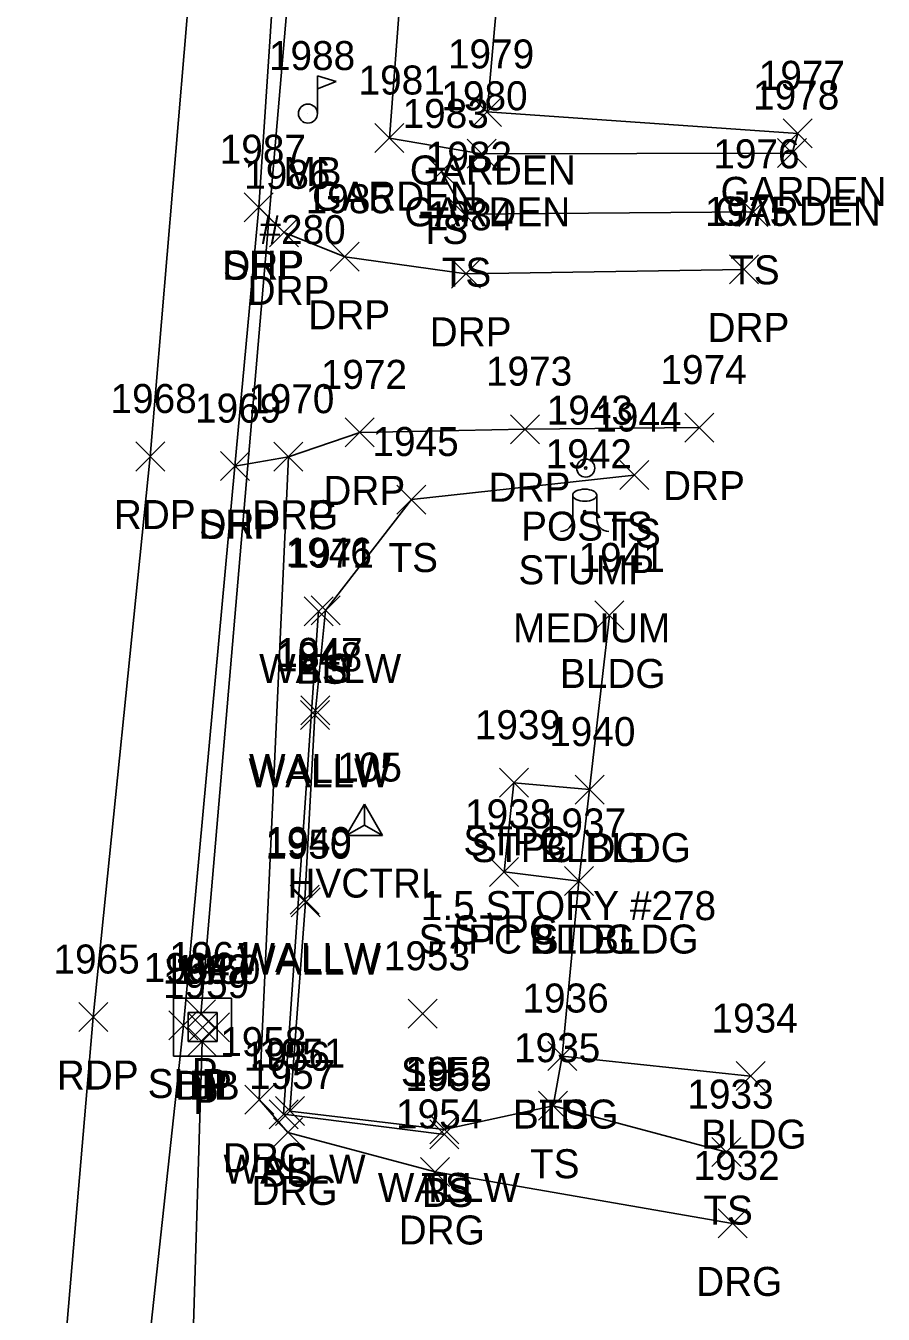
# Model space of a CAD drawing. Extents: x 1653908 to 1654393, y 539913 to 544256.
# Drawn here: x 1654094.1 to 1654153.2, y 541814.4 to 541903.2 of the extents above; entities that cross this region are included whole.
import ezdxf

# ---------------------------------------------------------------- set-up
doc = ezdxf.new("R2010")
doc.units = 0
for name, color, linetype in [('C_A', 7, 'Continuous'), ('C_I', 7, 'Continuous'), ('CPSM', 7, 'Continuous'), ('D_A', 7, 'Continuous'), ('D_I', 7, 'Continuous'), ('D_TIC', 7, 'Continuous'), ('DCP', 7, 'Continuous'), ('DS', 7, 'Continuous'), ('L_A', 7, 'Continuous'), ('L_C', 7, 'Continuous'), ('L_I', 7, 'Continuous'), ('L_TIC', 7, 'Continuous'), ('LAPB', 7, 'Continuous'), ('LBC', 7, 'Continuous'), ('LBF', 7, 'Continuous'), ('LELB', 7, 'Continuous'), ('LMB', 7, 'Continuous'), ('LPST', 7, 'Continuous'), ('LTS', 7, 'Continuous'), ('LW', 7, 'Continuous'), ('P_A', 7, 'Continuous'), ('P_I', 7, 'Continuous'), ('P_TIC', 7, 'Continuous'), ('PET', 7, 'Continuous'), ('PSP', 7, 'Continuous'), ('R_A', 7, 'Continuous'), ('R_I', 7, 'Continuous'), ('R_TIC', 7, 'Continuous'), ('RDG', 7, 'Continuous'), ('RDP', 7, 'Continuous')]:
    doc.layers.add(name, color=color, linetype=linetype)

msp = doc.modelspace()

# ---------------------------------------------------------------- linework, layer by layer
at = {"layer": 'CPSM'}
for p, q in [((1654116.189, 541847.419), (1654117.439, 541849.584)), ((1654118.689, 541847.419), (1654117.439, 541849.584)), ((1654117.439, 541848.141), (1654117.439, 541849.584)), ((1654116.189, 541847.419), (1654117.439, 541848.141)), ((1654117.439, 541848.141), (1654117.439, 541848.141)), ((1654117.439, 541848.141), (1654118.689, 541847.419)), ((1654116.189, 541847.419), (1654118.689, 541847.419))]:
    msp.add_line(p, q, dxfattribs=at)
at = {"layer": 'D_TIC'}
for points in [[(1654105.161, 541834.083), (1654107.161, 541836.083)], [(1654107.161, 541834.083), (1654105.161, 541836.083)], [(1654105.279, 541833.2), (1654107.279, 541835.2)], [(1654107.279, 541833.2), (1654105.279, 541835.2)], [(1654106.144, 541833.193), (1654108.144, 541835.193)], [(1654108.144, 541833.193), (1654106.144, 541835.193)], [(1654105.243, 541832.218), (1654107.243, 541834.218)], [(1654107.243, 541832.218), (1654105.243, 541834.218)]]:
    msp.add_lwpolyline(points, dxfattribs=at)
at = {"layer": 'DCP'}
for points in [[(1654106.161, 541835.083), (1654119.744, 541993.79)], [(1654099.929, 541626.87), (1654106.243, 541833.218)]]:
    msp.add_lwpolyline(points, dxfattribs=at)
at = {"layer": 'DS'}
for p, q in [((1654104.279, 541836.218), (1654108.279, 541836.218)), ((1654104.279, 541832.218), (1654104.279, 541836.218)), ((1654108.279, 541836.218), (1654108.279, 541832.218)), ((1654105.279, 541833.218), (1654105.279, 541835.218)), ((1654105.279, 541835.218), (1654107.279, 541835.218)), ((1654107.279, 541835.218), (1654107.279, 541833.218)), ((1654106.284, 541834.22), (1654106.284, 541834.22)), ((1654106.284, 541834.22), (1654106.284, 541834.22)), ((1654107.279, 541833.218), (1654105.279, 541833.218)), ((1654108.279, 541832.218), (1654104.279, 541832.218))]:
    msp.add_line(p, q, dxfattribs=at)
at = {"layer": 'L_TIC'}
for points in [[(1654124.903, 541896.3), (1654126.903, 541898.3)], [(1654126.903, 541896.3), (1654124.903, 541898.3)], [(1654118.161, 541894.504), (1654120.161, 541896.504)], [(1654120.161, 541894.504), (1654118.161, 541896.504)], [(1654146.333, 541894.826), (1654148.333, 541896.826)], [(1654148.333, 541894.826), (1654146.333, 541896.826)], [(1654146.333, 541894.826), (1654148.333, 541896.826)], [(1654148.333, 541894.826), (1654146.333, 541896.826)], [(1654124.528, 541893.416), (1654126.528, 541895.416)], [(1654126.528, 541893.416), (1654124.528, 541895.416)], [(1654145.94, 541893.469), (1654147.94, 541895.469)], [(1654147.94, 541893.469), (1654145.94, 541895.469)], [(1654121.766, 541892.198), (1654123.766, 541894.198)], [(1654123.766, 541892.198), (1654121.766, 541894.198)], [(1654123.364, 541889.248), (1654125.364, 541891.248)], [(1654125.364, 541889.248), (1654123.364, 541891.248)], [(1654143.256, 541889.415), (1654145.256, 541891.415)], [(1654145.256, 541889.415), (1654143.256, 541891.415)], [(1654135.058, 541871.272), (1654137.058, 541873.272)], [(1654137.058, 541871.272), (1654135.058, 541873.272)], [(1654119.689, 541869.583), (1654121.689, 541871.583)], [(1654121.689, 541869.583), (1654119.689, 541871.583)], [(1654113.275, 541861.879), (1654115.275, 541863.879)], [(1654115.275, 541861.879), (1654113.275, 541863.879)], [(1654113.76, 541861.944), (1654115.76, 541863.944)], [(1654115.76, 541861.944), (1654113.76, 541863.944)], [(1654113.76, 541861.944), (1654115.76, 541863.944)], [(1654115.76, 541861.944), (1654113.76, 541863.944)], [(1654133.337, 541861.593), (1654135.337, 541863.593)], [(1654135.337, 541861.593), (1654133.337, 541863.593)], [(1654113.028, 541854.738), (1654115.028, 541856.738)], [(1654115.028, 541854.738), (1654113.028, 541856.738)], [(1654113.065, 541855.045), (1654115.065, 541857.045)], [(1654115.065, 541855.045), (1654113.065, 541857.045)], [(1654126.757, 541850.059), (1654128.757, 541852.059)], [(1654128.757, 541850.059), (1654126.757, 541852.059)], [(1654131.967, 541849.586), (1654133.967, 541851.586)], [(1654133.967, 541849.586), (1654131.967, 541851.586)], [(1654131.967, 541849.586), (1654133.967, 541851.586)], [(1654133.967, 541849.586), (1654131.967, 541851.586)], [(1654126.074, 541843.911), (1654128.074, 541845.911)], [(1654128.074, 541843.911), (1654126.074, 541845.911)], [(1654131.237, 541843.284), (1654133.237, 541845.284)], [(1654133.237, 541843.284), (1654131.237, 541845.284)], [(1654131.237, 541843.284), (1654133.237, 541845.284)], [(1654133.237, 541843.284), (1654131.237, 541845.284)], [(1654112.331, 541842.001), (1654114.331, 541844.001)], [(1654114.331, 541842.001), (1654112.331, 541844.001)], [(1654112.379, 541841.825), (1654114.379, 541843.825)], [(1654114.379, 541841.825), (1654112.379, 541843.825)], [(1654120.468, 541834.131), (1654122.468, 541836.131)], [(1654122.468, 541834.131), (1654120.468, 541836.131)], [(1654130.089, 541831.217), (1654132.089, 541833.217)], [(1654132.089, 541831.217), (1654130.089, 541833.217)], [(1654130.089, 541831.217), (1654132.089, 541833.217)], [(1654132.089, 541831.217), (1654130.089, 541833.217)], [(1654143.073, 541829.834), (1654145.073, 541831.834)], [(1654145.073, 541829.834), (1654143.073, 541831.834)], [(1654129.452, 541827.794), (1654131.452, 541829.794)], [(1654131.452, 541827.794), (1654129.452, 541829.794)], [(1654129.452, 541827.794), (1654131.452, 541829.794)], [(1654131.452, 541827.794), (1654129.452, 541829.794)], [(1654110.869, 541827.203), (1654112.869, 541829.203)], [(1654112.869, 541827.203), (1654110.869, 541829.203)], [(1654111.303, 541827.419), (1654113.303, 541829.419)], [(1654113.303, 541827.419), (1654111.303, 541829.419)], [(1654121.946, 541826.162), (1654123.946, 541828.162)], [(1654123.946, 541826.162), (1654121.946, 541828.162)], [(1654121.946, 541826.162), (1654123.946, 541828.162)], [(1654123.946, 541826.162), (1654121.946, 541828.162)], [(1654121.963, 541825.816), (1654123.963, 541827.816)], [(1654123.963, 541825.816), (1654121.963, 541827.816)], [(1654141.407, 541824.595), (1654143.407, 541826.595)], [(1654143.407, 541824.595), (1654141.407, 541826.595)]]:
    msp.add_lwpolyline(points, dxfattribs=at)
at = {"layer": 'LAPB'}
for points in [[(1654147.333, 541895.826), (1654146.94, 541894.469), (1654125.528, 541894.416), (1654119.161, 541895.504), (1654120.598, 541914.299), (1654125.073, 541965.48)], [(1654147.333, 541895.826), (1654125.903, 541897.3), (1654127.425, 541914.47), (1654127.843, 541926.277), (1654125.891, 541926.542), (1654128.413, 541965.634), (1654125.073, 541965.48)]]:
    msp.add_lwpolyline(points, dxfattribs=at)
at = {"layer": 'LBC'}
msp.add_lwpolyline([(1654144.073, 541830.834), (1654131.089, 541832.217), (1654132.237, 541844.284), (1654132.967, 541850.586), (1654134.337, 541862.593)], dxfattribs=at)
at = {"layer": 'LBF'}
msp.add_lwpolyline([(1654132.237, 541844.284), (1654127.074, 541844.911), (1654127.757, 541851.059), (1654132.967, 541850.586)], dxfattribs=at)
at = {"layer": 'LELB'}
for points in [[(1654144.256, 541890.415), (1654124.364, 541890.248), (1654122.766, 541893.198)], [(1654136.058, 541872.272), (1654120.689, 541870.583), (1654114.76, 541862.944)], [(1654122.963, 541826.816), (1654111.869, 541828.203), (1654114.275, 541862.879)], [(1654130.452, 541828.794), (1654131.089, 541832.217)], [(1654142.407, 541825.595), (1654130.452, 541828.794), (1654122.946, 541827.162)]]:
    msp.add_lwpolyline(points, dxfattribs=at)
at = {"layer": 'LMB'}
for p, q in [((1654114.197, 541899.788), (1654115.491, 541899.406)), ((1654114.203, 541897.196), (1654114.202, 541899.791)), ((1654114.202, 541898.889), (1654115.484, 541899.397)), ((1654113.547, 541897.188), (1654113.547, 541897.188))]:
    msp.add_line(p, q, dxfattribs=at)
msp.add_circle((1654113.547, 541897.188), 0.656, dxfattribs=at)
at = {"layer": 'LPST'}
for radius in [0.625, 0.0833]:
    msp.add_circle((1654132.706, 541872.749), radius, dxfattribs=at)
at = {"layer": 'LTS'}
for p, q in [((1654131.808, 541870.878), (1654131.808, 541869.211)), ((1654133.475, 541870.711), (1654133.475, 541870.878)), ((1654133.475, 541870.878), (1654133.475, 541869.211)), ((1654132.641, 541869.736), (1654132.641, 541869.736)), ((1654132.641, 541869.736), (1654132.641, 541869.736)), ((1654132.641, 541869.711), (1654132.641, 541869.711))]:
    msp.add_line(p, q, dxfattribs=at)
msp.add_circle((1654132.641, 541869.736), 0.0833, dxfattribs=at)
for centre, start, end in [((1654130.975, 541869.211), 270, 360), ((1654134.308, 541869.211), 180, 270)]:
    msp.add_arc(centre, 0.833, start, end, dxfattribs=at)
msp.add_ellipse((1654132.641, 541870.878), major_axis=(-0.833, 0), ratio=0.5, dxfattribs=at)
at = {"layer": 'LW'}
msp.add_lwpolyline([(1654114.76, 541862.944), (1654114.065, 541856.045), (1654114.028, 541855.738), (1654113.331, 541843.001), (1654113.379, 541842.825), (1654112.303, 541828.419), (1654122.946, 541827.162)], dxfattribs=at)
at = {"layer": 'P_TIC'}
for points in [[(1654109.153, 541889.734), (1654111.153, 541891.734)], [(1654111.153, 541889.734), (1654109.153, 541891.734)], [(1654101.668, 541872.549), (1654103.668, 541874.549)], [(1654103.668, 541872.549), (1654101.668, 541874.549)], [(1654107.508, 541871.884), (1654109.508, 541873.884)], [(1654109.508, 541871.884), (1654107.508, 541873.884)], [(1654097.735, 541833.906), (1654099.735, 541835.906)], [(1654099.735, 541833.906), (1654097.735, 541835.906)], [(1654103.956, 541833.324), (1654105.956, 541835.324)], [(1654105.956, 541833.324), (1654103.956, 541835.324)]]:
    msp.add_lwpolyline(points, dxfattribs=at)
at = {"layer": 'PET'}
msp.add_lwpolyline([(1654079.776, 541659.551), (1654080.091, 541663.585), (1654084.434, 541705.035), (1654088.467, 541726.588), (1654090.823, 541750.421), (1654095.245, 541793.922), (1654098.735, 541834.906), (1654102.668, 541873.549), (1654106.19, 541915.359), (1654108.801, 541937.78), (1654112.78, 541976.541), (1654113.712, 541994.764), (1654118.507, 542040.261), (1654122.37, 542081.456), (1654125.512, 542120.567), (1654128.858, 542154.493), (1654132.07, 542197.521), (1654136.387, 542232.744)], dxfattribs=at)
at = {"layer": 'PSP'}
msp.add_lwpolyline([(1654094.458, 541721.214), (1654096.104, 541749.586), (1654101.261, 541800.15), (1654104.956, 541834.324), (1654108.508, 541872.884), (1654110.153, 541890.734), (1654111.767, 541915.009), (1654113.741, 541937.092), (1654116.462, 541969.541), (1654117.65, 541994.217), (1654121.735, 542040.282), (1654126.757, 542081.182), (1654129.731, 542120.034), (1654133.658, 542152.736), (1654138.064, 542196.396), (1654141.276, 542231.97)], dxfattribs=at)
at = {"layer": 'R_TIC'}
for points in [[(1654109.153, 541889.734), (1654111.153, 541891.734)], [(1654111.153, 541889.734), (1654109.153, 541891.734)], [(1654110.899, 541888.002), (1654112.899, 541890.002)], [(1654112.899, 541888.002), (1654110.899, 541890.002)], [(1654115.084, 541886.319), (1654117.084, 541888.319)], [(1654117.084, 541886.319), (1654115.084, 541888.319)], [(1654123.456, 541885.146), (1654125.456, 541887.146)], [(1654125.456, 541885.146), (1654123.456, 541887.146)], [(1654142.618, 541885.446), (1654144.618, 541887.446)], [(1654144.618, 541885.446), (1654142.618, 541887.446)], [(1654116.124, 541874.211), (1654118.124, 541876.211)], [(1654118.124, 541874.211), (1654116.124, 541876.211)], [(1654127.517, 541874.433), (1654129.517, 541876.433)], [(1654129.517, 541874.433), (1654127.517, 541876.433)], [(1654139.551, 541874.539), (1654141.551, 541876.539)], [(1654141.551, 541874.539), (1654139.551, 541876.539)], [(1654111.2, 541872.535), (1654113.2, 541874.535)], [(1654113.2, 541872.535), (1654111.2, 541874.535)], [(1654111.2, 541872.535), (1654113.2, 541874.535)], [(1654113.2, 541872.535), (1654111.2, 541874.535)], [(1654107.508, 541871.884), (1654109.508, 541873.884)], [(1654109.508, 541871.884), (1654107.508, 541873.884)], [(1654109.188, 541828.211), (1654111.188, 541830.211)], [(1654111.188, 541828.211), (1654109.188, 541830.211)], [(1654111.167, 541825.952), (1654113.167, 541827.952)], [(1654113.167, 541825.952), (1654111.167, 541827.952)], [(1654121.316, 541823.226), (1654123.316, 541825.226)], [(1654123.316, 541823.226), (1654121.316, 541825.226)], [(1654141.833, 541819.68), (1654143.833, 541821.68)], [(1654143.833, 541819.68), (1654141.833, 541821.68)]]:
    msp.add_lwpolyline(points, dxfattribs=at)
at = {"layer": 'RDG'}
msp.add_lwpolyline([(1654142.833, 541820.68), (1654122.316, 541824.226), (1654112.167, 541826.952), (1654110.188, 541829.211), (1654112.2, 541873.535)], dxfattribs=at)
at = {"layer": 'RDP'}
for points in [[(1654143.618, 541886.446), (1654124.456, 541886.146), (1654116.084, 541887.319), (1654111.899, 541889.002), (1654110.153, 541890.734)], [(1654108.508, 541872.884), (1654112.2, 541873.535), (1654117.124, 541875.211), (1654128.517, 541875.433), (1654140.551, 541875.539)]]:
    msp.add_lwpolyline(points, dxfattribs=at)

# ---------------------------------------------------------------- texts
at = {"layer": 'C_A'}
msp.add_text('HVCTRL', height=2, dxfattribs=at).set_placement((1654112.132, 541843.141))
at = {"layer": 'C_I'}
msp.add_text('105', height=2, dxfattribs=at).set_placement((1654115.565, 541851.141))
at = {"layer": 'D_A'}
for s, p in [('P', (1654105.539, 541830.083)), ('DIB', (1654104.381, 541829.2)), ('DI', (1654105.339, 541829.22)), ('P', (1654106.522, 541829.193)), ('P', (1654105.621, 541828.218))]:
    msp.add_text(s, height=2, dxfattribs=at).set_placement(p)
at = {"layer": 'D_I'}
for s, p in [('1961', (1654103.988, 541838.083)), ('1962', (1654103.539, 541837.2)), ('1963', (1654103.544, 541837.22)), ('1960', (1654104.318, 541837.193)), ('1959', (1654103.543, 541836.218))]:
    msp.add_text(s, height=2, dxfattribs=at).set_placement(p)
at = {"layer": 'L_A'}
for s, p in [('MB', (1654111.854, 541892.188)), ('GARDEN', (1654120.572, 541892.3)), ('GARDEN', (1654142.002, 541890.826)), ('GARDEN', (1654142.002, 541890.826)), ('GARDEN', (1654113.831, 541890.504)), ('GARDEN', (1654120.197, 541889.416)), ('GARDEN', (1654141.609, 541889.469)), ('TS', (1654121.176, 541888.198)), ('TS', (1654122.774, 541885.248)), ('TS', (1654142.666, 541885.415)), ('POSTS', (1654128.25, 541867.749)), ('TS', (1654134.467, 541867.272)), ('TS', (1654119.098, 541865.583)), ('STUMP', (1654128.062, 541864.738)), ('WALLW', (1654110.177, 541857.944)), ('BS', (1654112.716, 541857.879)), ('TS', (1654113.169, 541857.944)), ('BLDG', (1654130.927, 541857.593)), ('WALLW', (1654109.482, 541851.045)), ('WALLW', (1654109.446, 541850.738)), ('STPC', (1654124.269, 541846.059)), ('STPC BLDG', (1654124.802, 541845.586)), ('BLDG', (1654129.558, 541845.586)), ('STPC', (1654123.585, 541839.911)), ('STPC ST BLDG', (1654121.175, 541839.284)), ('BLDG', (1654128.828, 541839.284)), ('WALLW', (1654108.748, 541838.001)), ('WALLW', (1654108.797, 541837.825)), ('SH', (1654119.957, 541830.131)), ('BLDG', (1654127.68, 541827.217)), ('TS', (1654129.499, 541827.217)), ('BLDG', (1654140.664, 541825.834)), ('WALLW', (1654107.721, 541823.419)), ('TS', (1654128.861, 541823.794)), ('TS', (1654128.861, 541823.794)), ('BS', (1654110.31, 541823.203)), ('WALLW', (1654118.364, 541822.162)), ('TS', (1654121.356, 541822.162)), ('BS', (1654121.404, 541821.816)), ('TS', (1654140.816, 541820.595))]:
    msp.add_text(s, height=2, dxfattribs=at).set_placement(p)
at = {"layer": 'L_C'}
for s, p in [('#280', (1654110.201, 541888.188)), ('MEDIUM', (1654127.692, 541860.738)), ('1.5 STORY #278', (1654121.33, 541841.586))]:
    msp.add_text(s, height=2, dxfattribs=at).set_placement(p)
at = {"layer": 'L_I'}
for s, p in [('1988', (1654110.854, 541900.188)), ('1979', (1654123.202, 541900.3)), ('1977', (1654144.64, 541898.826)), ('1977', (1654144.64, 541898.826)), ('1981', (1654117.036, 541898.504)), ('1980', (1654122.749, 541897.416)), ('1978', (1654144.247, 541897.469)), ('1983', (1654120.074, 541896.198)), ('1982', (1654121.671, 541893.248)), ('1976', (1654141.508, 541893.415)), ('1943', (1654130.014, 541875.749)), ('1944', (1654133.365, 541875.272)), ('1945', (1654117.996, 541873.583)), ('1942', (1654129.944, 541872.738)), ('1946', (1654112.012, 541865.944)), ('1946', (1654112.012, 541865.944)), ('1971', (1654112.149, 541865.879)), ('1941', (1654132.211, 541865.593)), ('1947', (1654111.372, 541859.045)), ('1948', (1654111.336, 541858.738)), ('1939', (1654125.056, 541854.059)), ('1940', (1654130.188, 541853.586)), ('1940', (1654130.188, 541853.586)), ('1938', (1654124.381, 541847.911)), ('1937', (1654129.545, 541847.284)), ('1937', (1654129.545, 541847.284)), ('1950', (1654110.6, 541845.825)), ('1949', (1654110.63, 541846.001)), ('1953', (1654118.776, 541838.131)), ('1936', (1654128.341, 541835.217)), ('1936', (1654128.341, 541835.217)), ('1934', (1654141.38, 541833.834)), ('1951', (1654110.178, 541831.419)), ('1935', (1654127.759, 541831.794)), ('1935', (1654127.759, 541831.794)), ('1956', (1654109.121, 541831.203)), ('1952', (1654120.254, 541830.162)), ('1952', (1654120.254, 541830.162)), ('1955', (1654120.27, 541829.816)), ('1933', (1654139.714, 541828.595))]:
    msp.add_text(s, height=2, dxfattribs=at).set_placement(p)
at = {"layer": 'P_A'}
for s, p in [('SHP', (1654107.688, 541885.734)), ('RDP', (1654100.156, 541868.549)), ('SHP', (1654106.043, 541867.884)), ('RDP', (1654096.223, 541829.906)), ('SHP', (1654102.491, 541829.324))]:
    msp.add_text(s, height=2, dxfattribs=at).set_placement(p)
at = {"layer": 'P_I'}
for s, p in [('1987', (1654107.46, 541893.734)), ('1968', (1654099.928, 541876.549)), ('1969', (1654105.76, 541875.884)), ('1965', (1654095.995, 541837.906)), ('1964', (1654102.216, 541837.324))]:
    msp.add_text(s, height=2, dxfattribs=at).set_placement(p)
at = {"layer": 'R_A'}
for s, p in [('DRP', (1654107.641, 541885.734)), ('DRP', (1654109.387, 541884.002)), ('DRP', (1654113.572, 541882.319)), ('DRP', (1654121.944, 541881.146)), ('DRP', (1654141.106, 541881.446)), ('DRP', (1654126.005, 541870.433)), ('DRP', (1654138.039, 541870.539)), ('DRP', (1654114.612, 541870.211)), ('DRP', (1654105.996, 541867.884)), ('DRG', (1654109.688, 541868.535)), ('DRP', (1654109.688, 541868.535)), ('DRG', (1654107.676, 541824.211)), ('DRG', (1654109.656, 541821.952)), ('DRG', (1654119.804, 541819.226)), ('DRG', (1654140.321, 541815.68))]:
    msp.add_text(s, height=2, dxfattribs=at).set_placement(p)
at = {"layer": 'R_I'}
for s, p in [('1987', (1654107.46, 541893.734)), ('1986', (1654109.151, 541892.002)), ('1985', (1654113.391, 541890.319)), ('1984', (1654121.763, 541889.146)), ('1975', (1654140.925, 541889.446)), ('1973', (1654125.824, 541878.433)), ('1974', (1654137.858, 541878.539)), ('1972', (1654114.432, 541878.211)), ('1969', (1654105.76, 541875.884)), ('1970', (1654109.421, 541876.535)), ('1970', (1654109.421, 541876.535)), ('1958', (1654107.495, 541832.211)), ('1957', (1654109.475, 541829.952)), ('1954', (1654119.623, 541827.226)), ('1932', (1654140.14, 541823.68))]:
    msp.add_text(s, height=2, dxfattribs=at).set_placement(p)

doc.saveas('drawing.dxf')
